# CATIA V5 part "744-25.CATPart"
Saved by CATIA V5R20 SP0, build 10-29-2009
Part number: 744-25
Revision: TUTTO
Definition: NON CONOSCIUTO
Nomenclature: 744-25
Source: Unknown
Bounding box of the stored display mesh (mm): x -24 to 24, y -25 to 23.825, z -23 to 36
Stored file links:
  C:\Users\Utente\Desktop\IO LAVORO\3D X SITO CF\X SITO\744\744-25.CATPart
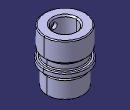
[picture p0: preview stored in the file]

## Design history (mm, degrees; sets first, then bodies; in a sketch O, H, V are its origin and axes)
Body1 "744-25 sol1" (main body)
  Solid1: solid without history
Body2 "IDV1M8_Ingrassatore-1"
  Solid2: solid without history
